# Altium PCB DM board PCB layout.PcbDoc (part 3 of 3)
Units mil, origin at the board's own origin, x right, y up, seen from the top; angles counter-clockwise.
Board outline 4444 x 6127 mil, 2 copper layers (Top Layer, Bottom Layer); 112 components, 94 nets, 2801 pads, 141 vias.
Unrouted connection lines stored in the file: 2.
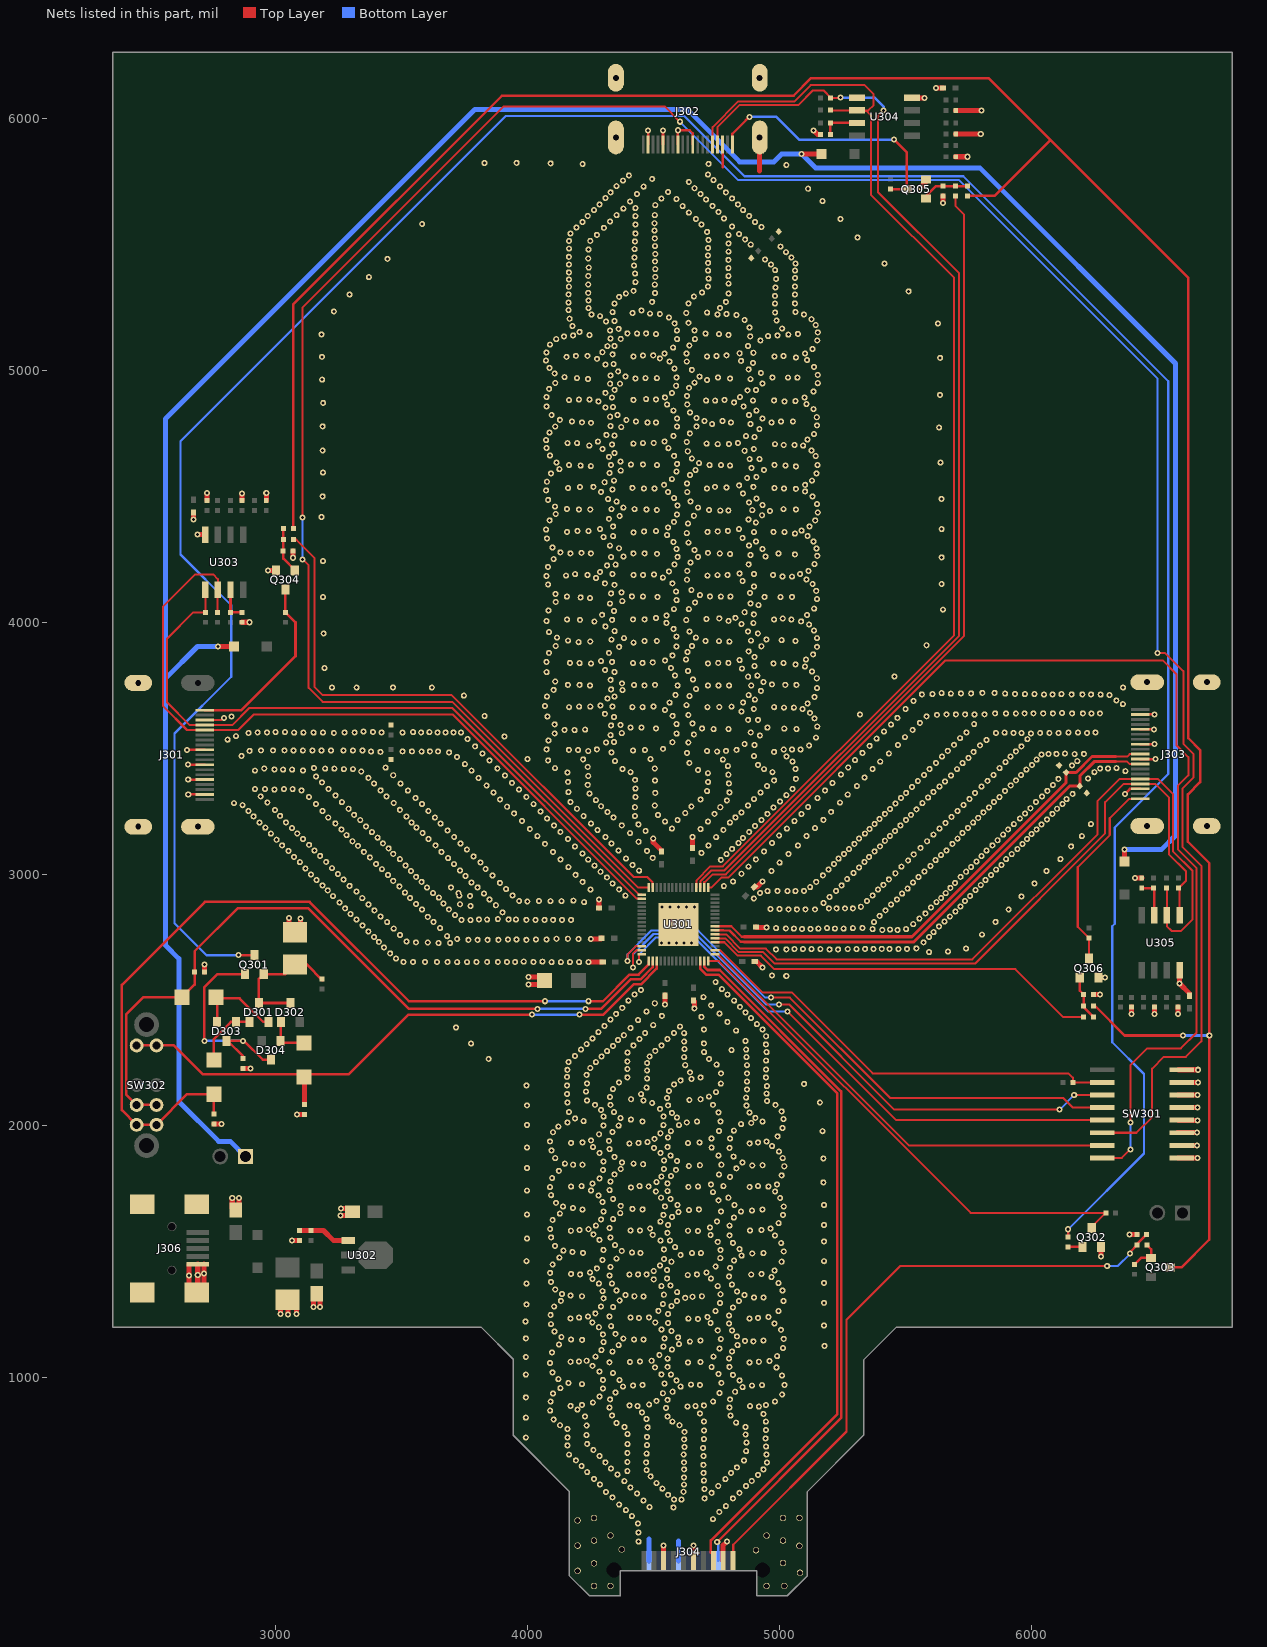
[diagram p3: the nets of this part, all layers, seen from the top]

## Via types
v1: diameter 24, hole 12, Top Layer to Bottom Layer, tented both sides, 141 vias

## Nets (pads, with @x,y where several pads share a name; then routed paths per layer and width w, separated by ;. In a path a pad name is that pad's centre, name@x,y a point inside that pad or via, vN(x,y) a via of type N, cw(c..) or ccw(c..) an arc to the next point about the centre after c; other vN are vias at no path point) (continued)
D33+: J303.10 R356.1 U301.40 | length 2028.5
  Top Layer w8: 6336,3466.15 6381.32,3466.15 6391,3475.83 J303.10@6433,3475.83
  Top Layer w9: U301.40@4745.67,2792.13 4778.39,2792.13 4779.01,2792.75 4809.25,2792.75 4851,2751 4861,2751
  Top Layer w12: 4861,2751 5526.72,2751 6138.92,3363.2 R356.1@6138.92,3403.08 6178.8,3403.08 6241.87,3466.15 6336,3466.15
D33-: J303.12 R357.1 U301.39 | length 2029.9
  Top Layer w8: 6336,3446.15 6381.32,3446.15 6391,3436.46 J303.12@6433,3436.46
  Top Layer w9: U301.39@4745.67,2776.38 4778.39,2776.38 4779.01,2775.75 4802.21,2775.75 4846.96,2731 4861,2731
  Top Layer w12: 4861,2731 5535,2731 6152.92,3348.92 R357.1@6193.08,3348.92 6193.08,3389.08 6250.15,3446.15 6336,3446.15
GND: C300.2 C301.2 C302.2 C303.2 C304.2 C305.2 C306.2 C307.2 C308.2 C309.2 C310.2 C314.2 C315.1 C316.1 C317.2 C318.2 C319.2 C320.2 C321.2 J301.2 J301.5 J301.8 J301.11 J301.17 J301.21 J301.22 J301.23 J302.2 J302.5 J302.8 J302.11 J302.17 J302.20 J302.21 J302.22 J302.23 J303.2 J303.5 J303.8 J303.11 J303.17 J303.20 J303.21 J303.22 J303.23 J304.2 J304.5 J304.8 J304.11 J304.17 J304.20 J306.5 pad. pad.0 pad.1 pad.2 pad.3 pad.4 pad.5 pad.6 pad.7 pad.8 pad.9 pad.10 pad.11 pad.12 pad.13 pad.14 pad.15 pad.16 pad.17 pad.18 pad.19 pad.20 pad.21 pad.22 pad.23 pad.24 pad.25 pad.26 pad.27 pad.28 pad.29 pad.30 pad.31 pad.32 pad.34 pad.35 pad.36 pad.37 pad.38 pad.39 pad.40 pad.41 pad.42 pad.43 pad.44 pad.45 pad.46 pad.47 pad.48 pad.49 pad.50 pad.51 pad.52 pad.53 pad.54 pad.55 pad.56 pad.57 pad.58 pad.59 pad.60 pad.61 pad.62 pad.63 pad.64 pad.65 pad.66 pad.67 pad.68 pad.69 pad.70 pad.71 pad.72 pad.73 pad.74 pad.75 pad.76 pad.77 pad.78 pad.79 pad.80 pad.81 pad.82 pad.83 pad.84 pad.85 pad.86 pad.87 pad.88 pad.89 pad.90 pad.91 pad.92 pad.93 pad.96 pad.97 pad.98 pad.99 pad.100 pad.101 pad.102 pad.103 pad.104 pad.105 pad.106 pad.107 pad.108 pad.109 pad.111 pad.112 pad.113 pad.114 pad.115 pad.116 pad.117 pad.118 pad.119 pad.120 pad.121 pad.122 pad.123 pad.124 pad.125 pad.126 pad.127 pad.128 pad.129 pad.130 pad.131 pad.132 pad.133 pad.134 pad.135 pad.136 pad.137 pad.138 pad.139 pad.140 pad.141 pad.142 pad.143 pad.144 pad.145 pad.148 pad.149 pad.150 pad.151 pad.152 pad.153 pad.154 pad.155 pad.156 pad.157 pad.158 pad.159 pad.160 pad.161 pad.162 pad.163 pad.164 Q302.2 Q304.2 Q305.2 Q306.2 R310.1 R313.2 R314.1 R315.1 R316.1 R317.1 R332.2 R333.2 R334.2 R335.2 R340.2 R341.2 R342.2 R343.2 R348.2 R349.2 R350.2 R351.2 R352.1 R353.1 R354.1 R356.2 R357.2 R358.2 R359.2 R360.2 R361.2 SW301.1 SW301.2 SW301.3 SW301.4 SW301.5 SW301.6 SW301.7 SW301.8 U301.65 U303.4 U304.4 U305.4 | length 4521.5
  Top Layer w8: J301.17@2720,3610.96 2786.04,3610.96
  Top Layer w10: v1(2649.15,3492.85) J301.11@2720,3492.85 ; v1(2653.2,3433.8) J301.8@2720,3433.8 ; v1(2654.26,3374.74) J301.5@2720,3374.74 ; v1(2654.31,3315.69) J301.2@2720,3315.69 ; J302.2@4479.69,5896 v1(4479.69,5950.69) ; J302.5@4538.74,5896 v1(4538.74,5950.74) ; J302.8@4597.8,5896 v1(4597.8,5952.2) 4644.8,5952.2 4656.85,5940.15 J302.11@4656.85,5896 ; 4774.96,5806.04 J302.17@4774.96,5896 ; v1(6372,3318) 6392.04,3338.04 J303.17@6433,3338.04 ; J303.11@6433,3456.15 v1(6492.85,3456.15) ; J303.8@6433,3515.2 v1(6490.2,3515.2) ; J303.5@6433,3574.26 v1(6487.26,3574.26) ; J303.2@6433,3633.31 v1(6490.31,3633.31)
  Top Layer w20: J306.5@2657,1373 J306.5@2657,1449 ; v1(2675,4408) C317.2@2675,4435 ; v1(2690.75,4347.25) U303.4@2722,4347.25 ; J306.5@2692.06,1369.94 J306.5@2692.06,1451.01 ; J306.5@2716,1371 J306.5@2716,1451 ; R315.1@2718.68,2611 v1(2718.68,2641.68) ; R334.2@2728,4482.69 v1(2728,4512) ; R314.1@2757,2007.32 v1(2785.68,2007.32) ; C321.2@2829,1675 v1(2829,1714) ; C321.2@2855,1682 v1(2855,1714) ; R335.2@2867,3999.31 v1(2897.69,3999.31) ; R333.2@2867,4482.69 v1(2867,4511) ; R317.1@2871,2228.32 v1(2900.68,2228.32) ; R332.2@2964,4482.68 v1(2964,4513) ; v1(2970,4205) Q304.2@3002,4205 ; v1(3021,1253) C314.2@3021,1292 ; v1(3050,1252) C314.2@3050,1283 ; C320.2@3055,2766 v1(3055,2826) ; v1(3066.32,1545.32) R313.2@3096,1545.32 ; v1(3070.68,4255.31) R352.1@3070.68,4283 ; v1(3084,1253) C314.2@3084,1284 ; v1(3085.32,2045.32) R316.1@3115,2045.32 ; C320.2@3100,2771 v1(3100,2824) ; v1(3151,1281) C315.1@3151,1335 ; v1(3178,1282) C315.1@3178,1313 ; v1(3258,1645) C316.1@3287,1645 ; v1(3261,1673) C316.1@3310,1673 ; v1(4004,2562) 4053.5,2562 C300.2@4068.5,2577 4053.5,2592 v1(4004,2592) ; pad.@4243,2650 C303.2@4299,2650 ; pad.@4252,2742 4292,2742 C302.2@4295,2745 ; C301.2@4285,2865 v1(4285,2899) ; pad.@4500,3141 4500,3126 C310.2@4528,3098 ; J304.5@4541.57,274 v1(4541.57,334) ; pad.@4546,2482 C304.2@4546,2520 ; C309.2@4656,3103 pad.@4656,3147 ; C305.2@4659,2498 4663,2494 pad.@4663,2467 ; J304.11@4659.69,274 v1(4659.69,335) ; J304.17@4777.8,274 4777.8,335.8 v1(4792,350) ; C308.2@4901.68,2948.68 4911.68,2948.68 v1(4934,2971) ; C306.2@4903,2652 4911,2652 v1(4934,2629) ; C307.2@4908,2790 4910,2788 pad.@4950,2788 ; 4922.6,5790.4 J302.20@4922.6,5923.52 ; v1(5136,5952) 5152,5936 R343.2@5163.31,5936 ; U304.4@5527.25,6081 v1(5576,6081) ; v1(5560,5725) 5582,5747 Q305.2@5582,5756 ; v1(5622,6120) C318.2@5650,6120 ; v1(5650,5664) R353.1@5650,5691.31 ; R340.2@5700.69,5847 v1(5747,5847) ; R341.2@5700.69,5938 v1(5800,5938) ; R342.2@5700.69,6030 v1(5803,6030) ; R354.1@6247.69,2522 v1(6274,2522) ; Q306.2@6268,2589 v1(6294,2589) ; v1(6278,1482) Q302.2@6278,1520 ; v1(6391,1569) R310.1@6419.31,1569 ; v1(6398,2445) R348.2@6398,2471.32 ; v1(6411.91,2983.68) R351.2@6439,2983.68 ; v1(6490,2445) R349.2@6490,2471.32 ; SW301.2@6580.52,1923 v1(6659,1923) ; SW301.3@6581,1974 v1(6658.48,1974) ; v1(6582,2444) R350.2@6582,2471.32 ; SW301.6@6583,2123 v1(6659.48,2123) ; SW301.1@6583.52,1873 v1(6660,1873) ; SW301.4@6584,2022 v1(6660.48,2022) ; SW301.8@6585,2223 v1(6661.48,2223) ; SW301.5@6585.52,2073 v1(6661,2073) ; SW301.7@6586,2173 v1(6662.48,2173) ; U305.4@6589,2617.75 v1(6589,2565) 6629,2525 C319.2@6629,2517
  Bottom Layer w20: J304.2@4482.52,274 4482.52,360.52 ; J304.8@4600.63,274 4600.63,353.37
  other v1: 2657,1407 2692.06,1409 2716,1414 5028,2596 4971,2597 4533,2727 4563,2727 4592,2727 4622,2727 4652,2727 4535,2869 4567,2869 4600,2869 4632,2869 4664,2869 2796,3619 2826,3626
HPD_A3: J301.19 Q304.3 R307.1 | length 735.3
  Top Layer w10: J301.19@2720,3650.33 2865.33,3650.33 3080,3865 3080,3998.68 R307.1@3040,4038.68 ; R307.1@3039.52,4033.83 Q304.3@3039.52,4130
HPD_A3_1: R323.1 U301.63 | length 2311.3
  Top Layer w8: R323.1@3071.68,4327 3083,4327 3154.97,4255.03 3154.97,3743.03 3188.01,3709.99 3700.01,3709.99 4422,2988 4476.17,2988 4495.81,2968.36 4497.64,2968.36 U301.63@4497.64,2945.67
HPD_B3: J302.19 Q305.3 R304.1 | length 1031.1
  Top Layer w10: J302.19@4814.33,5896 4814.33,5938.33 4868,5992 v1(4882,6005) ; R304.1@5442,5718.31 Q305.3@5506.83,5718.31 ; v1(5456,5915) 5507,5864 Q305.3@5507,5718.48
  Bottom Layer w10: v1(4882,6005) 4989,6005 5079,5915 v1(5456,5915)
HPD_B3_1: R325.1 U301.50 | length 3219.1
  Top Layer w8: U301.50@4702.36,2945.67 4702.36,2967.42 4704.19,2967.42 4735.77,2999 4788,2999 5734,3945 5734,5617 5699,5652 R325.1@5699,5691.31
HPD_C3: J303.19 Q306.3 R301.1 | length 782.2
  Top Layer w8: Q306.3@6230.48,2664 6230.48,2744.83 6185,2790.32 6185,3027 6312,3154 6312,3222 6388.67,3298.67 J303.19@6433,3298.67
HPD_C3_1: R327.1 U301.36 | length 1585.3
  Top Layer w8: U301.36@4745.67,2729.13 4781.87,2729.13 4835,2676 4927,2676 4981,2622 5937,2622 6126,2433 R327.1@6208.31,2433
HPD_D3: J304.19 R310.2 R321.1 | length 2481.1
  Top Layer w9: J304.19@4817.17,274 4817.17,337.17 5267,787 5267,1231 5480,1444 v1(6302,1444) ; v1(6393,1493) 6393,1499.68 R321.1@6420.31,1527
  Top Layer w10: R321.1@6420.31,1527 6420.31,1530.63 R310.2@6458.69,1569
  Bottom Layer w9: v1(6302,1444) 6344,1444 v1(6393,1493)
HPD_D3_1: Q302.3 R319.2 U301.32 | length 2075.3
  Top Layer w8: U301.32@4718.11,2654.33 4760.67,2654.33 5760,1655 R319.2@6296.31,1655 Q302.3@6240.48,1599.17
  Top Layer w10: Q302.3@6240.48,1595 Q302.3@6240.48,1599.17
NetC311_2: C311.2 D301.1 D303.1 | length 253.2
  Top Layer w10: C311.2@2756,2261 2756,2345 2824,2413 D301.1@2897,2413
NetC312_2: C312.2 D301.2 D303.2 | length 341.6
  Top Layer w10: C312.2@2764.5,2511 C312.2@2769,2506.5 ; D303.2@2769,2413 C312.2@2769,2506.5 ; D301.2@2972,2413 2952,2413 2858.5,2506.5 C312.2@2769,2506.5
NetC313_2: C313.2 D302.1 D304.1 | length 169.9
  Top Layer w10: D302.1@3022,2413 3022,2339 3031.5,2329.5 C313.2@3114,2329.5
NetC320_1: C320.1 D301.3 D302.3 Q301.2 R355.1 | length 523.9
  Top Layer w10: D302.3@3059.5,2488 D301.3@2934.5,2488 2934.5,2583.5 Q301.2@2954,2603 3040,2603 C320.1@3078,2641 3125,2641 R355.1@3188,2578
NetD303_3: D303.3 D304.3 Q301.1 R317.2 | length 852.8
  Top Layer w10: v1(2718,2338) 2718,2551 2770,2603 Q301.1@2879,2603 ; D303.3@2806.48,2338 2875,2338 2950,2263 D304.3@2983.48,2263 ; D303.3@2811,2338 2871,2278 R317.2@2871,2267.68
  Bottom Layer w10: v1(2718,2338) v1(2872,2338)
NetD305_2: D305.2 D306.2 D307.2 JP302.1 | length 10598.5
  Top Layer w20: v1(2773,3903) D305.2@2836,3903 ; v1(5089,5858) D306.2@5168,5858 ; D307.2@6371,3049 v1(6371,3098)
  Bottom Layer w20: 2563.5,3775.5 2691,3903 v1(2773,3903) ; JP302.1@2881,1879 2821,1939 2775,1939 2617,2097 2617,2664 2564,2717 2564,4806.75 3792.25,6035 4635.38,6035 4843.38,5827 4979,5827 5010,5858 v1(5089,5858) 5144,5803 5796,5803 6573,5026 6573,3153 6518,3098 v1(6371,3098)
NetQ301_3: Q301.3 R318.2 | length 11014.6
  Top Layer w9: v1(2853,2678) Q301.3@2916.5,2678 ; R318.2@6147,1559.68 v1(6147,1590)
  Bottom Layer w9: v1(2853,2678) 2727,2678 2600,2805 2600,3558 2825,3783 2825,4067 2624,4268 2624,4718 3915,6009 4623,6009 4862,5770 5730,5770 6544,4956 6544,3397 6332,3185 6332,2803 6322,2793 6322,2332 6448,2206 6448,1891 v1(6147,1590)
NetQ302_1: Q302.1 R318.1 | length 56.1
  Top Layer w10: R318.1@6147,1520.32 6147.31,1520 Q302.1@6203,1520
NetQ303_1: Q303.1 R320.1 R321.2 | length 133.2
  Top Layer w10: R320.1@6411,1450.68 6436.32,1476 Q303.1@6476,1476 6476,1510.69 R321.2@6459.69,1527
NetQ303_3: Q303.3 R322.2 R324.1 R326.1 | length 10164.7
  Top Layer w10: R322.2@3071.68,4372 3071.68,5261.69 3899,6089 5057,6089 5127,6159 5831,6159 6624,5366 6624,3539 6671,3492 6671,3365 6622,3316 6622,3128 6707,3043 6707,1549 6596.5,1438.5 Q303.3@6551,1438.5 ; R324.1@5748,5691.31 5854.52,5691.31 6076.6,5913.4 ; R326.1@6247.69,2477 6253,2477 6371,2359 v1(6602,2359)
  Bottom Layer w10: v1(6602,2359) v1(6707,2359)
NetQ304_1: Q304.1 R322.1 R323.2 R352.2 | length 185.5
  Top Layer w10: R322.1@3032.32,4372 3032.32,4251.69 3077,4207 Q304.1@3077,4205
NetQ305_1: Q305.1 R324.2 R325.2 R353.2 | length 192.4
  Top Layer w10: Q305.1@5582,5681 5582,5691 5621.69,5730.69 R324.2@5748,5730.69
NetQ306_1: Q306.1 R326.2 R327.2 R354.2 | length 178.7
  Top Layer w10: Q306.1@6193,2589 6193,2537.32 R354.2@6208.31,2522 6208.31,2472.37 R327.2@6247.69,2433
NetR311_2: R311.2 SW301.10 U301.34 | length 1772.9
  Top Layer w8: U301.34@4745.67,2697.64 4765.36,2697.64 4933,2530 5050,2530 5371,2209 6148,2209 6165.69,2191.32 R311.2@6165.69,2173 SW301.10@6282.52,2173 ; R311.2@6160.34,2175.66 R311.2@6168.34,2175.66
NetR312_1: R312.1 R313.1 U302.1 | length 209.4
  Top Layer w20: R313.1@3096,1584.68 3191.32,1584.68 3229.94,1546.06 U302.1@3289.37,1546.06
NetSW301_11: SW301.11 U301.15 | length 2356.6
  Top Layer w8: v1(4419,2629) 4419,2683 4433.64,2697.64 U301.15@4454.33,2697.64 ; v1(4999,2482) 5040,2482 5457,2065 v1(6113,2065) ; v1(6171,2123) SW301.11@6282.52,2123
  Bottom Layer w8: v1(4419,2629) 4419,2680 4501,2762 4669,2762 4949,2482 v1(4999,2482) ; v1(6113,2065) v1(6171,2123)
NetSW301_12: SW301.12 U301.14 | length 2336.6
  Top Layer w8: v1(4398,2655) 4398,2681 4430.39,2713.39 U301.14@4454.33,2713.39 ; v1(4967,2509) 5042,2509 5440,2111 6128,2111 6166,2073 SW301.12@6282.52,2073
  Bottom Layer w8: v1(4398,2655) 4398,2682 4491,2775 4679,2775 4945,2509 v1(4967,2509)
NetSW301_13: SW301.13 U301.16 | length 2240.8
  Top Layer w8: v1(4443.89,2649.89) 4443.89,2681.89 U301.16@4454.33,2681.89 ; v1(5032,2455) 5464,2023 SW301.13@6282.52,2023
  Bottom Layer w8: v1(4443.89,2649.89) 4443.89,2681.89 4510,2748 4662,2748 4955,2455 v1(5032,2455)
NetSW301_14: SW301.14 U301.64 | length 10783.1
  Top Layer w8: v1(3108,4249) 3132,4225 3132,3739 3187.98,3683.02 3702.98,3683.02 4440,2946 4471,2946 ; v1(3108,4415) 3108,5249 3906,6047 4545,6047 v1(4606,5986) ; 4470.33,2945.67 U301.64@4481.89,2945.67 ; SW301.14@6282.52,1973 6418,1973 6480,2035 6480,2227 6527,2274 6614,2274 6676,2336 6676,3032 6601,3107 6601,3340 6645,3384 6645,3476 6604,3517 6604,3805 6531,3878 v1(6502,3878)
  Bottom Layer w8: v1(3108,4249) v1(3108,4415) ; v1(4606,5986) 4838,5754 5714,5754 6502,4966 v1(6502,3878)
NetSW301_15: SW301.15 U301.33 | length 1851.2
  Top Layer w8: U301.33@4745.67,2681.89 4756.11,2681.89 5515,1923 SW301.15@6282.52,1923
NetSW301_16: SW301.16 U301.49 | length 4521.8
  Top Layer w8: U301.49@4718.11,2945.67 4730,2945.67 4770.33,2986 4798,2986 5660,3848 6522,3848 6577,3793 6577,3511 6624,3464 6624,3392 6582,3350 6582,3098 6657,3023 6657,2371 6594,2308 6461,2308 6394,2241 v1(6394,2013) ; SW301.16@6282.52,1873 6360,1873 v1(6394,1907)
  Bottom Layer w8: v1(6394,1907) v1(6394,2013)
PORT1_3: C311.1 R314.2 SW302.4 SW302.8 U301.17 | length 3479
  Top Layer w10: R314.2@2756,2047.68 C311.1@2756,2126 2649.85,2126 SW302.4@2528.37,2004.52 SW302.8@2449.63,2004.52 2391,2063.15 2391,2560 2720,2889 3136,2889 3530,2495 v1(4071,2495) ; v1(4243,2495) 4300,2495 4405.5,2600.5 4441.5,2600.5 4481.89,2640.89 U301.17@4481.89,2654.33
  Bottom Layer w10: v1(4071,2495) v1(4243,2495)
PORT2_3: C312.1 R315.2 SW302.3 SW302.7 U301.18 | length 3056.2
  Top Layer w10: SW302.3@2528.37,2083.26 SW302.7@2449.63,2083.26 2408,2124.89 2408,2443 2476,2511 C312.1@2629.5,2511 2679.32,2560.82 2679.32,2693.32 2851,2865 3130,2865 3530,2465 v1(4041,2465) ; v1(4232,2465) 4293,2465 4410,2582 4449.79,2582 4497.64,2629.85 U301.18@4497.64,2654.33
  Bottom Layer w10: v1(4041,2465) v1(4232,2465)
PORT3_3: C313.1 R316.2 SW302.1 SW302.5 U301.19 | length 2422.8
  Top Layer w10: SW302.5@2449.63,2319.48 2597.52,2319.48 2711,2206 3292,2206 3528,2442 v1(4019,2442) ; v1(4207,2442) 4302,2442 4422,2562 4451,2562 4513.39,2624.39 U301.19@4513.39,2654.33
  Top Layer w20: R316.2@3115,2084.68 C313.1@3115,2193.5
  Bottom Layer w10: v1(4019,2442) v1(4207,2442)
SCL_A3: J301.15 R309.2 U301.2 U303.6 | length 3072.1
  Top Layer w8: R309.2@2770,4038.68 2770,4126.75 U303.6@2772,4128.75 2772,4170 2753,4189 2682,4189 2555,4062 2555,3666 2649.41,3571.59 2852.59,3571.59 2914,3633 3704,3633 4434.64,2902.36 U301.2@4454.33,2902.36
SCL_B3: J302.15 R306.2 U301.52 U304.6 | length 4741.7
  Top Layer w8: U301.52@4670.87,2945.67 4670.87,2973.87 4727,3030 4776,3030 5694,3948 5694,5366 5365,5695 5365,6010 5347,6028 5303,6028 U304.6@5300,6031 ; J302.15@4735.59,5896 4735.59,5964.59 4838,6067 5061,6067 5125,6131 5339,6131 5375,6095 5375,6052 5354,6031 R306.2@5203.69,6031
SCL_C3: J303.15 R303.2 U301.38 U305.6 | length 3068.2
  Top Layer w8: U301.38@4745.67,2760.63 4789.37,2760.63 4846,2704 4947,2704 4990,2661 5767,2661 6264,3158 6264,3290 6351.41,3377.41 6502.59,3377.41 6564,3316 6564,3089 6641,3012 6641,2820 6595,2774 6557,2774 6539,2792 6539,2943.32 R303.2@6538,2944.32
SCL_D3: J304.15 U301.30 | length 2847
  Top Layer w10: U301.30@4686.61,2654.33 4686.61,2623.39 4687.36,2623.39 4709.75,2601 4759,2601 5231,2129 5231,857.25 4729,355.25 4729,306.09 4738.43,296.67 J304.15@4738.43,274
SDA_A3: J301.16 R308.2 U301.1 U303.5 | length 2794.3
  Top Layer w8: U303.5@2722,4128.75 R308.2@2722,4038.68 2674.68,4038.68 2570,3934 2570,3682 2660.72,3591.28 2829.28,3591.28 2897,3659 3703,3659 4443.89,2918.11 U301.1@4454.33,2918.11
SDA_B3: J302.16 R305.2 U301.51 U304.5 | length 4512.7
  Top Layer w8: U301.51@4686.61,2945.67 4686.61,2970.36 4730.25,3014 4782,3014 5714,3946 5714,5384 5393,5705 5393,6009 v1(5414,6030) ; J302.16@4755.28,5896 4755.28,5965.28 4842,6052 5075,6052 5133,6110 5176,6110 5205,6081 v1@5244,6081
  Bottom Layer w10: v1(5244,6082) 5378,6082 5414,6046 v1(5414,6030)
SDA_C3: J303.16 R302.2 U301.37 U305.5 | length 2737.4
  Top Layer w8: U301.37@4745.67,2744.88 4785.12,2744.88 4840,2690 4936,2690 4982,2644 5777,2644 6294,3161 6294,3285 6366.72,3357.72 6492.28,3357.72 6548,3302 6548,3077 6615,3010 6615,2974.32 R302.2@6585,2944.32 ; U305.5@6589,2836.25 R302.2@6589,2940.32
SDA_D3: J304.16 U301.31 | length 2839.7
  Top Layer w10: U301.31@4702.36,2654.33 4702.36,2631.64 4703.19,2631.64 4715.83,2619 4764,2619 5246,2137 5246,841 v1(4754,349)
  Bottom Layer w10: v1(4754,349) 4758.11,344.89 J304.16@4758.11,274
WP_A3: R331.2 R335.1 U303.7 | length 135.1
  Top Layer w10: U303.7@2822,4128.75 R331.2@2822,4038.68 R335.1@2867,4038.68
WP_B3: R339.2 R343.1 U304.7 | length 151.1
  Top Layer w10: R343.1@5202.69,5936 R339.2@5202.69,5981 U304.7@5308.75,5981
WP_C3: R347.2 R351.1 U305.7 | length 156.3
  Top Layer w10: R351.1@6439,2944.32 R347.2@6486,2944.32 6489,2941.32 U305.7@6489,2836.25
pads on no net: D302.2 D304.2 J301.14 J301.20 J302.14 J303.14 J304.14 J304.41 J306.2 J306.3 J306.4 J306.10 J306.11 SW301.9 SW302.9 SW302.10

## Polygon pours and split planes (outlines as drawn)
+3V3_3 on Top Layer "bottom Layer-No Net" (solid, pour order 1000): 3125,1563 3165,1563 3220,1508 3308,1508 3352,1552 3352,1707 3532,1707 3532,1382 3390,1382 3316,1456 3310,1462 3185,1462 3125,1462 3125,1563
GND on Top Layer "bottom Layer-No Net" (solid, remove dead copper, pour order 1000): 3940.99,1074.64 3940.99,772.01 4214,499 4393.64,319.36 4883.36,319.36 5336,772 5336,812 5336,2261 6388.99,3313.99 6388.99,3762.64 5675.99,4475.64 5675.99,5194.01 5022,5848 3807.31,5848 3765.92,5806.61 3162.86,5203.55 3162.86,4916 3162.86,4036.86 3125,3999 2765,3639 2765,3632 2765,3307 2937,3135 3940.99,2131.01 3940.99,1061.99
GND on Bottom Layer "bottom Layer-No Net" (solid, remove dead copper, pour order 1002): 4406,319 4886,319 5118,551 5338,771 5338,820 5338,1072 5464,1198 6800,1198 6798,1200 6798,6261 2355,6261 2355,1199 3820,1199 3942,1077 3943,1076 3943,1010 3943,769 4164,548 4393,319 4406,319

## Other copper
Top Layer:
  pour cut-out: 4474,2928 4728,2928 4728,2676 4472,2676 4471,2677 4474,2680

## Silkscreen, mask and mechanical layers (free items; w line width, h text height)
Top Overlay:
  text "PI3HDMI301 QFN-64 2-layer DEMO BOARD" at 2635,5480 h80
  text "REV.B" at 2630,5360 h80
  text "OE#" at 5905,2150 h60
  text "OC_S0" at 5900,2095 h60
  text "OC_S1" at 5900,2045 h60
  text "OC_S2" at 5900,1995 h60
  text "OC_S3" at 5895,1949.08 h60
  text "EQ_S0" at 5900,1905 h60
  text "EQ_S1" at 5900,1850 h60
Bottom Overlay:
  text "0940DB038" at 6697,1238 h60
Mechanical 1:
  the board outline again, w8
